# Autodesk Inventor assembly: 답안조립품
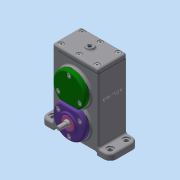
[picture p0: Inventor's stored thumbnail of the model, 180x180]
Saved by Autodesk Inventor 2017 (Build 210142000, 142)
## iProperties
Part Number: 답안조립품
Material: 일반
Document SubType Name: Assembly
Designer: 222
Author: 222
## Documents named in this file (24)
- C:\Users\222\Desktop\600506V1017\답안조립품.iam
- C:\Users\222\Desktop\600506V1017\본체.ipt
- C:\Users\222\Desktop\600506V1017\Ű 4 x 4 x 12.ipt
- C:\Users\222\Desktop\600506V1017\Ű 5 x 5 x 12.ipt
- C:\Users\222\Desktop\600506V1017\개스킷 A.ipt
- C:\Users\222\Desktop\600506V1017\개스킷 B.ipt
- C:\Users\222\Desktop\600506V1017\개스킷 C.ipt
- C:\Users\222\Desktop\600506V1017\베어링 6001.ipt
- 베어링 6001.ipt
- C:\Users\222\Desktop\600506V1017\베어링 6002.ipt
- 베어링 6002.ipt
- C:\Users\222\Desktop\600506V1017\볼트 M4.ipt
- C:\Users\222\Desktop\600506V1017\스퍼기어 A.ipt
- C:\Users\222\Desktop\600506V1017\스퍼기어 B.ipt
- C:\Users\222\Desktop\600506V1017\오일 실 10 20 7.ipt
- C:\Users\222\Desktop\600506V1017\오일 실 12 22 7.ipt
- C:\Users\222\Desktop\600506V1017\축 A.ipt
- C:\Users\222\Desktop\600506V1017\축 B.ipt
- C:\Users\222\Desktop\600506V1017\칼라.ipt
- C:\Users\222\Desktop\600506V1017\커버 A.ipt
- C:\Users\222\Desktop\600506V1017\커버 B.ipt
- C:\Users\222\Desktop\600506V1017\커버 C.ipt
- C:\Users\222\Desktop\600506V1017\커버 D.ipt
- C:\Users\222\Desktop\600506V1017\커버 E.ipt
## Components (7 placed, 5 different names)
1. Ű 4 x 4 x 12:1
2. Ű 5 x 5 x 12:1
3. 개스킷 A:1
4. 개스킷 B:1
5. 개스킷 C:1
6. 개스킷 B:2
7. 개스킷 B:3
